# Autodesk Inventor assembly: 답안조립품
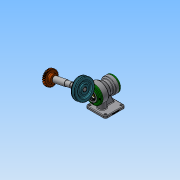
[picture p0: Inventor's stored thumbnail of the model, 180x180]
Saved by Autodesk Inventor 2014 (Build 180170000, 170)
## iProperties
Created: 2019-01
Part Number: 답안조립품
Document SubType Name: Assembly
Designer: NET
Author: NET
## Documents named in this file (15)
- C:\Users\NET\Desktop\490107V1007\답안조립품.iam
- C:\Users\NET\Desktop\490107V1007\본체.ipt
- C:\Users\NET\Desktop\490107V1007\V-벨트풀리.ipt
- C:\Users\NET\Desktop\490107V1007\뒤커버.ipt
- C:\Users\NET\Desktop\490107V1007\멈춤나사 M3.ipt
- C:\Users\NET\Desktop\490107V1007\베어링 6203.ipt
- C:\Users\NET\Desktop\490107V1007\베어링 6205.ipt
- C:\Users\NET\Desktop\490107V1007\볼트 M4.ipt
- C:\Users\NET\Desktop\490107V1007\스퍼기어.ipt
- C:\Users\NET\Desktop\490107V1007\앞커버.ipt
- C:\Users\NET\Desktop\490107V1007\오일 실 17 30 8.ipt
- C:\Users\NET\Desktop\490107V1007\오일 실 25 38 8.ipt
- C:\Users\NET\Desktop\490107V1007\축.ipt
- C:\Users\NET\Desktop\490107V1007\키 5 x 5 x 20.ipt
- C:\Users\NET\Desktop\490107V1007\키 6 x 6 x 18.ipt
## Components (1 placed, 1 different names)
1. V-벨트풀리:1 — 각도:3
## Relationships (1: Angle 1)
- 각도:3 [Angle]: V-벨트풀리:1
